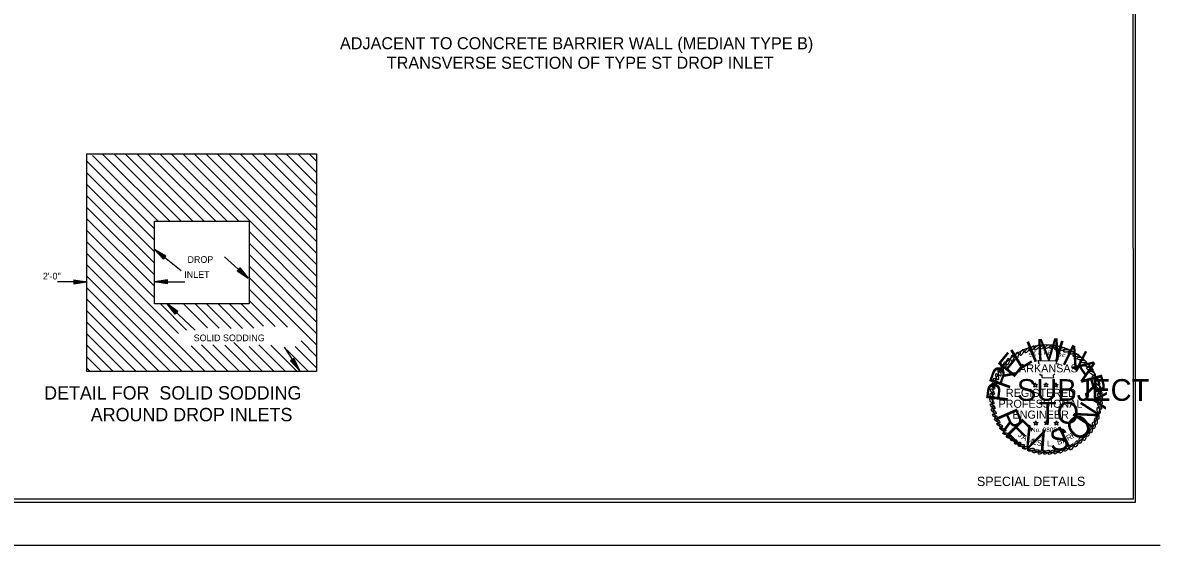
# Model space of a CAD drawing. Extents: x 714919 to 718439, y 1619644 to 1621844.
# Drawn here: x 716492 to 718439, y 1619644 to 1620539 of the extents above; entities that cross this region are included whole.
import ezdxf

# ---------------------------------------------------------------- set-up
doc = ezdxf.new("R2010")
doc.units = 0
for name, color, linetype in [('R_Annotation', 7, 'Continuous'), ('R_Border', 7, 'Continuous'), ('R_Border Notes', 7, 'Continuous'), ('R_Border PE', 7, 'Continuous'), ('R_Border Prem', 7, 'Continuous'), ('R_Dimension', 7, 'Continuous'), ('R_Draft', 7, 'Continuous'), ('R_No Plot', 7, 'Continuous')]:
    doc.layers.add(name, color=color, linetype=linetype)

msp = doc.modelspace()

# ---------------------------------------------------------------- linework, layer by layer
at = {"layer": 'R_Border'}
for p, q in [((718393.2, 1619722.5), (718393.1, 1621777.1)), ((718393.2, 1619722.5), (715231.2, 1619722.5)), ((714919.1, 1619643.5), (718439.3, 1619643.8))]:
    msp.add_line(p, q, dxfattribs=at)
at = {"layer": 'R_Border PE'}
for points in [[(718232.2, 1619953.8), (718230.1, 1619960.3), (718262.7, 1619959.4), (718260.3, 1619955), (718265.3, 1619954.7), (718265, 1619954.1)], [(718258.8, 1619937.5), (718256.1, 1619934.6), (718256.7, 1619930.1), (718237.2, 1619930.7), (718237.2, 1619934.9), (718233.7, 1619934.9), (718233.7, 1619937.5)]]:
    msp.add_lwpolyline(points, dxfattribs=at)
for points in [[(718225.4, 1619921.8), (718226.3, 1619918.9), (718229.2, 1619918.9), (718226.8, 1619917.4), (718227.7, 1619914.4), (718225.4, 1619916.2), (718223, 1619914.4), (718223.9, 1619917.4), (718221.5, 1619918.9), (718224.5, 1619918.9)], [(718243.7, 1619922.1), (718244.6, 1619919.5), (718247.3, 1619919.5), (718245.2, 1619917.7), (718246.1, 1619915), (718243.7, 1619916.5), (718241.3, 1619915), (718242.2, 1619917.7), (718239.9, 1619919.5), (718242.8, 1619919.5)], [(718260.6, 1619921.8), (718261.5, 1619918.9), (718264.4, 1619918.9), (718262.1, 1619917.4), (718263, 1619914.4), (718260.6, 1619916.2), (718258.2, 1619914.4), (718259.1, 1619917.4), (718256.7, 1619918.9), (718259.7, 1619918.9)], [(718226.3, 1619857), (718227.1, 1619854), (718230.1, 1619854), (718227.7, 1619852.6), (718228.6, 1619849.6), (718226.3, 1619851.4), (718223.9, 1619849.6), (718224.8, 1619852.6), (718222.4, 1619854), (718225.4, 1619854)], [(718244.6, 1619857.3), (718245.5, 1619854.6), (718248.2, 1619854.6), (718245.8, 1619852.9), (718247, 1619850.2), (718244.6, 1619851.7), (718242.2, 1619850.2), (718243.1, 1619852.9), (718240.8, 1619854.6), (718243.7, 1619854.6)], [(718261.5, 1619857), (718262.4, 1619854), (718265.3, 1619854), (718263, 1619852.6), (718263.8, 1619849.6), (718261.5, 1619851.4), (718259.1, 1619849.6), (718260, 1619852.6), (718257.6, 1619854), (718260.6, 1619854)]]:
    msp.add_lwpolyline(points, close=True, dxfattribs=at)
for centre, major_axis, ratio in [((718211.5, 1619978), (-3.58, -4.44), 0.329518), ((718219.6, 1619980.9), (-3.64, -4.4), 0.329518), ((718228.4, 1619982.7), (-4.59, -4.21), 0.348728), ((718236.7, 1619983.2), (-3.87, -3.02), 0.44237), ((718246.4, 1619984.1), (-4.21, -2.45), 0.475469), ((718255.1, 1619983.2), (-4.21, -2.45), 0.475469), ((718263.2, 1619981.7), (-4.21, -2.45), 0.475469), ((718271.2, 1619979.7), (-4.64, -1.48), 0.475469), ((718178.3, 1619958.3), (-1.53, -5.49), 0.391724), ((718186.2, 1619964.6), (-1.53, -5.49), 0.394697), ((718194.1, 1619969.1), (-1.53, -5.49), 0.375751), ((718202.5, 1619974), (-2.46, -5.15), 0.329518), ((718278.6, 1619976.9), (-4.79, -0.89), 0.475469), ((718286.5, 1619973.3), (-4.85, -0.42), 0.475469), ((718294.8, 1619969), (-4.85, -0.42), 0.475469), ((718301.4, 1619963.9), (-4.87, 0.11), 0.475469), ((718164, 1619939), (1.57, -5.48), 0.322879), ((718168.4, 1619946.2), (0, -5.7), 0.322879), ((718173.1, 1619952.2), (0, -5.7), 0.322879), ((718307, 1619958.6), (-5.09, 0.7), 0.451028), ((718313.3, 1619952.2), (-5.17, 1.18), 0.436264), ((718318.5, 1619945.9), (-5.3, 1.59), 0.418512), ((718322.8, 1619938.7), (-4.99, 2.77), 0.40589), ((718156.7, 1619924.4), (1.57, -5.48), 0.322879), ((718160.2, 1619932.3), (1.57, -5.48), 0.322879), ((718327.8, 1619930.8), (-4.66, 3.28), 0.40589), ((718330.9, 1619922.8), (-4.3, 3.75), 0.40589), ((718151.4, 1619898.8), (3.04, -4.83), 0.322879), ((718151.9, 1619906.9), (3.04, -4.83), 0.322879), ((718153.5, 1619916.3), (1.57, -5.48), 0.322879), ((718333.5, 1619914.9), (-4.3, 3.75), 0.40589), ((718335.2, 1619907.3), (-4.1, 3.96), 0.40589), ((718336.1, 1619898.9), (-3.5, 4.5), 0.40589), ((718150.9, 1619890.4), (3.04, -4.83), 0.322879), ((718152.3, 1619881.7), (3.92, -4.14), 0.322879), ((718335.8, 1619882.1), (-2.3, 5.22), 0.40589), ((718336.3, 1619890.7), (-2.77, 4.99), 0.40589), ((718154.2, 1619873.4), (3.92, -4.14), 0.322879), ((718156.7, 1619864.6), (4.29, -3.76), 0.322879), ((718331.9, 1619864.8), (-1.02, 5.61), 0.40589), ((718333.7, 1619874.3), (-1.48, 5.51), 0.40589), ((718160.1, 1619857), (4.67, -3.27), 0.322879), ((718164.3, 1619849.4), (5.13, -2.49), 0.322879), ((718169.6, 1619842.1), (5.13, -2.49), 0.322879), ((718320.9, 1619841.8), (0.27, 5.7), 0.40589), ((718325.4, 1619849.4), (-0.33, 5.69), 0.40589), ((718329.2, 1619856.2), (-0.33, 5.69), 0.40589), ((718175.6, 1619834.4), (5.58, -1.19), 0.322879), ((718181.3, 1619828.6), (5.58, -1.19), 0.322879), ((718188.3, 1619823.6), (5.58, -1.19), 0.322879), ((718302.8, 1619823.7), (1.36, 5.54), 0.40589), ((718309.7, 1619828.6), (0.91, 5.63), 0.40589), ((718315.2, 1619835.6), (0.91, 5.63), 0.40589), ((718195.1, 1619818.5), (5.68, 0.48), 0.322879), ((718201.8, 1619814.6), (5.68, 0.48), 0.322879), ((718209, 1619810.8), (5.68, 0.48), 0.40589), ((718218, 1619807.3), (5.5, 1.52), 0.40589), ((718226.3, 1619804.7), (5.5, 1.52), 0.40589), ((718235.5, 1619803.3), (4.91, 2.91), 0.40589), ((718244.7, 1619803.2), (4.91, 2.91), 0.40589), ((718252.8, 1619803.1), (4.63, 3.33), 0.40589), ((718261.9, 1619804.4), (4.36, 3.68), 0.40589), ((718270.3, 1619805.7), (4.08, 3.98), 0.40589), ((718279, 1619809.5), (3.39, 4.59), 0.40589), ((718287.4, 1619812.2), (2.43, 5.16), 0.40589), ((718295.4, 1619817.3), (2.26, 5.24), 0.40589)]:
    msp.add_ellipse(centre, major_axis=major_axis, ratio=ratio, dxfattribs=at)
at = {"layer": 'R_Border Prem'}
msp.add_circle((718244.5, 1619894.9), 92.6, dxfattribs=at)
at = {"layer": 'R_Dimension'}
for p, q in [((716732.6, 1620133.8), (716717.2, 1620150.3)), ((716736.8, 1620139), (716717.2, 1620150.3)), ((716763, 1620113.9), (716717.3, 1620150.3)), ((716732.9, 1620134.2), (716720.2, 1620148)), ((716736.4, 1620138.6), (716720.2, 1620148)), ((716736.1, 1620138.1), (716723.2, 1620145.6)), ((716733.3, 1620134.7), (716723.2, 1620145.6)), ((716733.7, 1620135.1), (716726.1, 1620143.3)), ((716735.7, 1620137.7), (716726.1, 1620143.3)), ((716735.4, 1620137.3), (716729, 1620140.9)), ((716734, 1620135.6), (716729, 1620140.9)), ((716735, 1620136.8), (716732, 1620138.6)), ((716734.4, 1620136), (716732, 1620138.6)), ((716732.6, 1620133.8), (716736.8, 1620139)), ((716836.9, 1620138), (716877.6, 1620101.6)), ((716863.3, 1620118.9), (716858.8, 1620113.9)), ((716861.8, 1620117.3), (716866.4, 1620111.6)), ((716862.1, 1620117.7), (716869.3, 1620109.1)), ((716862.5, 1620118.1), (716872, 1620106.6)), ((716862.9, 1620118.5), (716874.9, 1620104.1)), ((716863.3, 1620118.9), (716877.7, 1620101.6)), ((716579.3, 1620098.3), (716601.6, 1620095)), ((716579.3, 1620098.3), (716579.3, 1620091.6)), ((716579.3, 1620097.8), (716597.9, 1620095)), ((716739.4, 1620098.3), (716717.2, 1620095)), ((716739.4, 1620097.8), (716720.9, 1620095)), ((716739.4, 1620091.6), (716739.4, 1620098.3)), ((716858.8, 1620113.9), (716877.7, 1620101.6)), ((716859.2, 1620114.4), (716874.9, 1620104.1)), ((716859.6, 1620114.8), (716872, 1620106.6)), ((716859.9, 1620115.2), (716869.3, 1620109.1)), ((716860.3, 1620115.6), (716866.4, 1620111.6)), ((716860.7, 1620116.1), (716863.7, 1620114.1)), ((716861.4, 1620116.8), (716863.7, 1620114.1)), ((716601.6, 1620095), (716551.4, 1620095)), ((716579.3, 1620097.2), (716594, 1620095)), ((716579.3, 1620096.7), (716590.3, 1620095)), ((716579.3, 1620096.1), (716586.6, 1620095)), ((716579.3, 1620095.5), (716582.8, 1620095)), ((716579.3, 1620091.6), (716601.6, 1620095)), ((716579.3, 1620093.9), (716586.6, 1620095)), ((716579.3, 1620092.8), (716594, 1620095)), ((716579.3, 1620092.2), (716597.9, 1620095)), ((716579.3, 1620093.3), (716590.3, 1620095)), ((716579.3, 1620094.5), (716582.8, 1620095)), ((716717.2, 1620095), (716769.2, 1620095)), ((716739.4, 1620091.6), (716717.2, 1620095)), ((716739.4, 1620092.2), (716720.9, 1620095)), ((716739.4, 1620097.2), (716724.7, 1620095)), ((716739.4, 1620092.8), (716724.7, 1620095)), ((716739.4, 1620096.7), (716728.4, 1620095)), ((716739.4, 1620093.3), (716728.4, 1620095)), ((716739.4, 1620096.1), (716732.2, 1620095)), ((716739.4, 1620093.9), (716732.2, 1620095)), ((716739.4, 1620095.5), (716735.9, 1620095)), ((716739.4, 1620094.5), (716735.9, 1620095)), ((716752.8, 1620039.5), (716738.9, 1620057.1)), ((716757.4, 1620044.3), (716738.9, 1620057.1)), ((716786.9, 1620012.1), (716738.9, 1620057.1)), ((716753.2, 1620039.9), (716741.6, 1620054.6)), ((716757, 1620043.9), (716741.6, 1620054.6)), ((716756.7, 1620043.5), (716744.4, 1620052)), ((716753.6, 1620040.3), (716744.4, 1620052)), ((716754, 1620040.7), (716747.1, 1620049.4)), ((716756.3, 1620043.1), (716747.1, 1620049.4)), ((716755.9, 1620042.7), (716749.9, 1620046.8)), ((716754.4, 1620041.1), (716749.9, 1620046.8)), ((716755.5, 1620042.3), (716752.6, 1620044.3)), ((716754.8, 1620041.5), (716752.6, 1620044.3)), ((716752.8, 1620039.5), (716757.4, 1620044.3)), ((716939.1, 1619983.2), (716965.4, 1619942.9)), ((716956, 1619963.4), (716950.4, 1619959.8)), ((716952.7, 1619961.3), (716955.1, 1619958.7)), ((716953.6, 1619961.9), (716955.1, 1619958.7)), ((716954.1, 1619962.2), (716957.1, 1619955.5)), ((716954.6, 1619962.5), (716959.2, 1619952.4)), ((716955, 1619962.8), (716961.2, 1619949.3)), ((716955.5, 1619963.1), (716963.3, 1619946.1)), ((716956, 1619963.4), (716965.4, 1619942.9)), ((716950.4, 1619959.8), (716965.4, 1619942.9)), ((716950.8, 1619960.1), (716963.3, 1619946.1)), ((716951.3, 1619960.4), (716961.2, 1619949.3)), ((716951.8, 1619960.7), (716959.2, 1619952.4)), ((716952.3, 1619961), (716957.1, 1619955.5))]:
    msp.add_line(p, q, dxfattribs=at)
at = {"layer": 'R_Draft'}
for p, q in [((716627.8, 1620314.6), (716743.4, 1620199)), ((716647.5, 1620314.6), (716763.1, 1620199)), ((716667.2, 1620314.6), (716782.7, 1620199)), ((716686.9, 1620314.6), (716802.4, 1620199)), ((716706.6, 1620314.6), (716822.1, 1620199)), ((716726.2, 1620314.6), (716841.8, 1620199)), ((716745.9, 1620314.6), (716861.5, 1620199)), ((716765.6, 1620314.6), (716994.9, 1620085.3)), ((716785.3, 1620314.6), (716994.9, 1620105)), ((716805, 1620314.6), (716994.9, 1620124.7)), ((716824.7, 1620314.6), (716994.9, 1620144.4)), ((716844.4, 1620314.6), (716994.9, 1620164.1)), ((716864.1, 1620314.6), (716994.9, 1620183.7)), ((716883.8, 1620314.6), (716994.9, 1620203.4)), ((716903.5, 1620314.6), (716994.9, 1620223.1)), ((716923.1, 1620314.6), (716994.9, 1620242.8)), ((716942.8, 1620314.6), (716994.9, 1620262.5)), ((716962.5, 1620314.6), (716994.9, 1620282.2)), ((716982.2, 1620314.6), (716994.9, 1620301.9)), ((716601.3, 1620301.7), (716717.2, 1620185.9)), ((716611.2, 1620311.5), (716723.7, 1620199)), ((716601.6, 1620281.7), (716717.2, 1620166.2)), ((716601.6, 1620262), (716717.2, 1620146.5)), ((716601.6, 1620242.4), (716717.2, 1620126.8)), ((716601.6, 1620222.7), (716717.2, 1620107.1)), ((716601.6, 1620203), (716717.2, 1620087.4)), ((716601.6, 1620183.3), (716717.2, 1620067.7)), ((716879.3, 1620181.2), (716994.9, 1620065.6)), ((716601.6, 1620163.6), (716758.5, 1620006.7)), ((716879.3, 1620161.5), (716994.9, 1620045.9)), ((716601.6, 1620143.9), (716804, 1619941.5)), ((716879.3, 1620141.8), (716994.9, 1620026.2)), ((716601.6, 1620124.2), (716784.3, 1619941.5)), ((716879.3, 1620122.1), (716994.9, 1620006.5)), ((716601.6, 1620104.5), (716764.6, 1619941.5)), ((716879.3, 1620102.4), (716994.9, 1619986.9)), ((716601.6, 1620084.8), (716744.9, 1619941.5)), ((716879.3, 1620082.7), (716945, 1620017.1)), ((716601.6, 1620065.1), (716725.2, 1619941.5)), ((716879.3, 1620063), (716924.1, 1620018.3)), ((716601.6, 1620045.5), (716705.6, 1619941.5)), ((716727.8, 1620057.1), (716772.3, 1620012.5)), ((716767.2, 1620057.1), (716808.3, 1620016)), ((716786.9, 1620057.1), (716828, 1620015.9)), ((716806.6, 1620057.1), (716848.4, 1620015.2)), ((716826.3, 1620057.1), (716868.1, 1620015.2)), ((716846, 1620057.1), (716887.3, 1620015.7)), ((716865.6, 1620057.1), (716903.8, 1620018.9)), ((716601.6, 1620025.8), (716685.9, 1619941.5)), ((716601.6, 1620006.1), (716666.2, 1619941.5)), ((716601.6, 1619986.4), (716646.5, 1619941.5)), ((716780, 1619985.2), (716823.7, 1619941.5)), ((716797.9, 1619987), (716843.4, 1619941.5)), ((716817.4, 1619987.2), (716863.1, 1619941.5)), ((716837.7, 1619986.5), (716882.8, 1619941.5)), ((716853, 1619991), (716902.5, 1619941.5)), ((716879.3, 1619984.3), (716922.1, 1619941.5)), ((716896.1, 1619987.2), (716941.8, 1619941.5)), ((716916.4, 1619986.6), (716961.5, 1619941.5)), ((716958.4, 1619984), (716994.9, 1619947.5)), ((716968.3, 1619993.8), (716994.9, 1619967.2)), ((716601.6, 1619966.7), (716626.8, 1619941.5)), ((716944, 1619978.7), (716981.2, 1619941.5)), ((716601.6, 1619947), (716607.1, 1619941.5))]:
    msp.add_line(p, q, dxfattribs=at)
for points in [[(716601.6, 1620314.6), (716994.9, 1620314.6), (716994.9, 1619941.5), (716601.6, 1619941.5)], [(716717.2, 1620199), (716879.3, 1620199), (716879.3, 1620057.1), (716717.2, 1620057.1)]]:
    msp.add_lwpolyline(points, close=True, dxfattribs=at)
at = {"layer": 'R_No Plot'}
msp.add_lwpolyline([(715227.2, 1619717.3), (718397.1, 1619717.4), (718397.2, 1621782.5), (715227.1, 1621782.3)], close=True, dxfattribs=at)

# ---------------------------------------------------------------- texts
at = {"layer": 'R_Annotation'}
for s, height, p in [('ADJACENT TO CONCRETE BARRIER WALL (MEDIAN TYPE B) ', 20.734, (717034.9, 1620493.6)), ('TRANSVERSE SECTION OF TYPE ST DROP INLET', 20.734, (717115, 1620460.2)), ('DETAIL FOR  SOLID SODDING', 22.888, (716528.4, 1619893.3)), ('AROUND DROP INLETS', 22.888, (716608.2, 1619856.1))]:
    msp.add_text(s, height=height, dxfattribs=at).set_placement(p)
at = {"layer": 'R_Border Notes'}
msp.add_text('SPECIAL DETAILS', height=16, rotation=359.9984, dxfattribs=at).set_placement((718125.4, 1619745.1))
at = {"layer": 'R_Border PE'}
for s, height, rotation, p in [('S', 6.91, 19.5814, (718215.3, 1619965.6)), ('T', 6.91, 14.9614, (718222.7, 1619968)), ('A', 6.91, 5.7216, (718230.1, 1619969.8)), ('T', 6.91, 1.1017, (718238.4, 1619970.4)), ('E', 6.91, 356.4818, (718246.4, 1619970.4)), ('O', 6.91, 342.6221, (718261.8, 1619968.3)), ('F', 6.91, 338.0022, (718269.5, 1619965.9)), ('ARKANSAS', 13.81, 360, (718197.5, 1619939.9)), ('REGISTERED', 13.81, 360, (718175, 1619897.9)), ('PROFESSIONAL', 13.814, 360, (718162.3, 1619879.2)), ('ENGINEER', 13.81, 360, (718186.3, 1619860.6)), ('No. 9808', 7.89, 360, (718218.1, 1619837.5)), ('J', 9.6, 322.4167, (718194.5, 1619831.2)), ('A', 9.6, 328.0171, (718201, 1619826.4)), ('M', 9.6, 333.6175, (718209.3, 1619821.6)), ('E', 9.6, 344.8183, (718218.8, 1619817.5)), ('B', 9.6, 18.4207, (718264.1, 1619815.3)), ('A', 9.6, 24.0211, (718272.9, 1619818)), ('R', 9.6, 29.6215, (718281.7, 1619822)), ('R', 9.6, 35.2219, (718289.6, 1619826.8)), ('S', 9.6, 350.4187, (718227.2, 1619815.1)), ('L', 9.6, 1.6195, (718245.5, 1619813.2)), ('.', 9.6, 7.2199, (718254.4, 1619813.8))]:
    msp.add_text(s, height=height, rotation=rotation, dxfattribs=at).set_placement(p)
at = {"layer": 'R_Border Prem'}
for s, height, rotation, p in [('I', 37.2, 22.0105, (718219.9, 1619955.5)), ('M', 37.2, 2.6943, (718228, 1619959.6)), ('I', 37.2, 343.3781, (718254.3, 1619960.2)), ('N', 37.2, 333.7199, (718268.9, 1619955.7)), ('E', 37.2, 50.9849, (718187.3, 1619928.3)), ('L', 37.2, 31.6686, (718198.3, 1619943.3)), ('R', 37.2, 70.3011, (718179.9, 1619908.7)), ('A', 37.2, 304.7456, (718286.4, 1619949.1)), ('SUBJECT', 37.24, 360, (718193.8, 1619891.1)), ('R', 37.2, 285.4294, (718302.5, 1619930.3)), ('P', 37.2, 82.6089, (718177.4, 1619887)), ('Y', 37.2, 266.1131, (718311.1, 1619910.3)), ('TO', 37.24, 360, (718231.4, 1619852)), ('N', 37.2, 57.1378, (718318.1, 1619842.4)), ('R', 37.2, 293.7639, (718158.1, 1619866.7)), ('O', 37.2, 36.5754, (718295.4, 1619820.2)), ('E', 37.2, 314.3262, (718174.1, 1619837.5)), ('V', 37.2, 334.8885, (718197.2, 1619817.2)), ('S', 37.2, 5.732, (718251.5, 1619804.8)), ('I', 37.2, 26.2943, (718276.5, 1619809.9)), ('I', 37.2, 355.4508, (718230, 1619805.4))]:
    msp.add_text(s, height=height, rotation=rotation, dxfattribs=at).set_placement(p)
at = {"layer": 'R_Dimension'}
for s, height, p in [('DROP', 11.44, (716773.8, 1620127.6)), ('2\'-0"', 11.44, (716526.2, 1620099.1)), ('INLET', 11.44, (716768.3, 1620101.8)), ('SOLID SODDING', 11.444, (716784.4, 1619993.3))]:
    msp.add_text(s, height=height, dxfattribs=at).set_placement(p)

doc.saveas('drawing.dxf')
